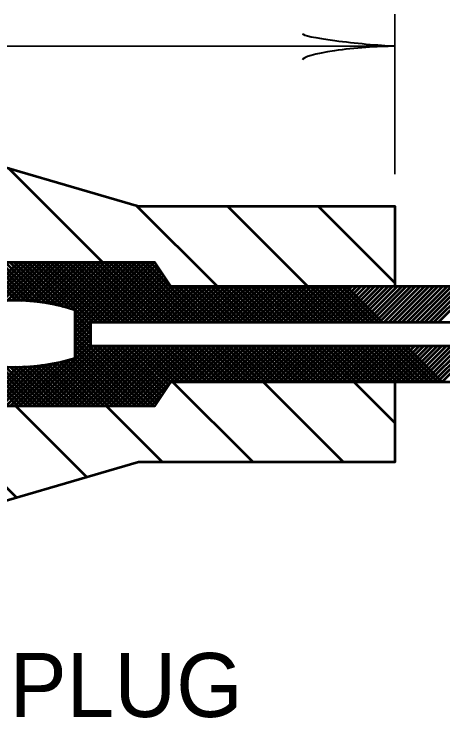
# Model space of a CAD drawing. Extents: x -1 to 679, y 0 to 440.
# Drawn here: x 534.27 to 547.66, y 229.08 to 251.07 of the extents above; entities that cross this region are included whole.
import ezdxf

# ---------------------------------------------------------------- set-up
doc = ezdxf.new("R2010")
doc.units = 0
doc.header["$LTSCALE"] = 0.8
doc.layers.add('1', color=7, linetype='Continuous', lineweight=53)

msp = doc.modelspace()

# ---------------------------------------------------------------- linework, layer by layer
at = {"layer": '1', "lineweight": 35}
for p, q in [((546.1543, 246.0712), (546.1543, 251.0712)), ((484.1543, 250.0712), (546.1543, 250.0712))]:
    msp.add_line(p, q, dxfattribs=at)
at = {"layer": '1'}
for p, q in [((537.0252, 243.3212), (534.0897, 246.2567)), ((540.6036, 242.5712), (538.0828, 245.0922)), ((543.4321, 242.5712), (540.9321, 245.0712)), ((546.1543, 242.6774), (543.7605, 245.0712)), ((533.0808, 241.9989), (534.4032, 243.3212)), ((534.3386, 242.1226), (533.14, 243.3212)), ((533.2508, 242.0275), (534.5447, 243.3212)), ((534.4863, 242.1162), (533.2814, 243.3212)), ((533.4209, 242.0561), (534.6861, 243.3212)), ((534.6341, 242.1099), (533.4228, 243.3212)), ((534.7818, 242.1037), (533.5643, 243.3212)), ((533.5909, 242.0847), (534.8275, 243.3212)), ((534.9397, 242.0872), (533.7057, 243.3212)), ((533.7446, 242.0969), (534.9689, 243.3212)), ((535.1057, 242.0626), (533.8471, 243.3212)), ((533.8953, 242.1062), (535.1103, 243.3212)), ((535.2718, 242.0379), (533.9885, 243.3212)), ((534.0461, 242.1156), (535.2518, 243.3212)), ((535.438, 242.0132), (534.1299, 243.3212)), ((534.1969, 242.125), (535.3932, 243.3212)), ((535.6254, 241.9672), (534.2713, 243.3212)), ((534.3361, 242.1227), (535.5346, 243.3212)), ((535.8159, 241.9181), (534.4127, 243.3212)), ((534.4717, 242.1169), (535.676, 243.3212)), ((536.0065, 241.869), (534.5542, 243.3212)), ((534.6073, 242.1111), (535.8174, 243.3212)), ((536.6637, 241.3532), (534.6956, 243.3212)), ((534.7429, 242.1053), (535.9588, 243.3212)), ((536.712, 241.4462), (534.837, 243.3212)), ((534.8757, 242.0967), (536.1002, 243.3212)), ((536.8534, 241.4462), (534.9784, 243.3212)), ((534.9989, 242.0784), (536.2417, 243.3212)), ((536.9949, 241.4462), (535.1199, 243.3212)), ((535.122, 242.0602), (536.3831, 243.3212)), ((535.2452, 242.0418), (536.5245, 243.3212)), ((537.1363, 241.4462), (535.2613, 243.3212)), ((535.3682, 242.0236), (536.6659, 243.3212)), ((537.2777, 241.4462), (535.4027, 243.3212)), ((535.4886, 242.0024), (536.8074, 243.3212)), ((537.4192, 241.4462), (535.5442, 243.3212)), ((535.601, 241.9735), (536.9488, 243.3212)), ((537.5606, 241.4462), (535.6856, 243.3212)), ((535.7135, 241.9445), (537.0902, 243.3212)), ((535.8259, 241.9155), (537.2317, 243.3212)), ((537.702, 241.4462), (535.827, 243.3212)), ((535.9383, 241.8865), (537.3731, 243.3212)), ((537.8434, 241.4462), (535.9684, 243.3212)), ((536.0507, 241.8576), (537.5145, 243.3212)), ((537.9848, 241.4462), (536.1098, 243.3212)), ((536.1578, 241.8232), (537.6559, 243.3212)), ((536.1637, 241.6876), (537.7973, 243.3212)), ((536.1637, 241.5462), (537.9388, 243.3212)), ((536.1637, 241.4047), (538.0802, 243.3212)), ((536.1637, 241.2633), (538.2216, 243.3212)), ((536.1637, 241.1219), (538.363, 243.3212)), ((536.1637, 240.9805), (538.5044, 243.3212)), ((538.1263, 241.4462), (536.2513, 243.3212)), ((538.2677, 241.4462), (536.3927, 243.3212)), ((538.4091, 241.4462), (536.5341, 243.3212)), ((538.5505, 241.4462), (536.6755, 243.3212)), ((536.7708, 241.4462), (538.6458, 243.3212)), ((538.6919, 241.4462), (536.8169, 243.3212)), ((536.9122, 241.4462), (538.7075, 243.2415)), ((538.8333, 241.4462), (536.9583, 243.3212)), ((538.9747, 241.4462), (537.0997, 243.3212)), ((539.1162, 241.4462), (537.2412, 243.3212)), ((539.2576, 241.4462), (537.3826, 243.3212)), ((539.399, 241.4462), (537.524, 243.3212)), ((539.5405, 241.4462), (537.6655, 243.3212)), ((539.6819, 241.4462), (537.8069, 243.3212)), ((539.8233, 241.4462), (537.9483, 243.3212)), ((539.9647, 241.4462), (538.0897, 243.3212)), ((540.1062, 241.4462), (538.2312, 243.3212)), ((540.2476, 241.4462), (538.3726, 243.3212)), ((538.935, 242.9002), (538.514, 243.3212)), ((537.0537, 241.4462), (538.7641, 243.1567)), ((537.1951, 241.4462), (538.8207, 243.0717)), ((537.3365, 241.4462), (538.8773, 242.9869)), ((537.478, 241.4462), (538.9338, 242.9021)), ((537.6194, 241.4462), (538.9903, 242.8173)), ((537.7608, 241.4462), (539.0469, 242.7323)), ((537.9022, 241.4462), (539.1035, 242.6475)), ((538.0437, 241.4462), (539.1687, 242.5712)), ((538.1851, 241.4462), (539.3101, 242.5712)), ((538.3265, 241.4462), (539.4515, 242.5712)), ((538.4679, 241.4462), (539.5929, 242.5712)), ((538.6093, 241.4462), (539.7343, 242.5712)), ((538.7507, 241.4462), (539.8757, 242.5712)), ((538.8922, 241.4462), (540.0172, 242.5712)), ((539.0336, 241.4462), (540.1586, 242.5712)), ((539.175, 241.4462), (540.3, 242.5712)), ((540.389, 241.4462), (539.264, 242.5712)), ((539.3164, 241.4462), (540.4414, 242.5712)), ((540.5304, 241.4462), (539.4054, 242.5712)), ((539.4578, 241.4462), (540.5828, 242.5712)), ((540.6718, 241.4462), (539.5468, 242.5712)), ((539.5992, 241.4462), (540.7242, 242.5712)), ((540.8132, 241.4462), (539.6882, 242.5712)), ((539.7407, 241.4462), (540.8657, 242.5712)), ((540.9547, 241.4462), (539.8297, 242.5712)), ((539.8822, 241.4462), (541.0072, 242.5712)), ((541.0961, 241.4462), (539.9711, 242.5712)), ((540.0236, 241.4462), (541.1486, 242.5712)), ((541.2375, 241.4462), (540.1125, 242.5712)), ((540.165, 241.4462), (541.29, 242.5712)), ((541.3789, 241.4462), (540.2539, 242.5712)), ((540.3064, 241.4462), (541.4314, 242.5712)), ((541.5203, 241.4462), (540.3953, 242.5712)), ((540.4478, 241.4462), (541.5728, 242.5712)), ((541.6617, 241.4462), (540.5367, 242.5712)), ((540.5892, 241.4462), (541.7142, 242.5712)), ((541.8032, 241.4462), (540.6782, 242.5712)), ((540.7307, 241.4462), (541.8557, 242.5712)), ((541.9446, 241.4462), (540.8196, 242.5712)), ((540.8721, 241.4462), (541.9971, 242.5712)), ((542.0861, 241.4462), (540.9611, 242.5712)), ((541.0135, 241.4462), (542.1385, 242.5712)), ((542.2275, 241.4462), (541.1025, 242.5712)), ((541.1549, 241.4462), (542.2799, 242.5712)), ((542.3689, 241.4462), (541.2439, 242.5712)), ((541.2963, 241.4462), (542.4213, 242.5712)), ((542.5103, 241.4462), (541.3853, 242.5712)), ((541.4377, 241.4462), (542.5627, 242.5712)), ((542.6517, 241.4462), (541.5267, 242.5712)), ((541.5792, 241.4462), (542.7042, 242.5712)), ((542.7932, 241.4462), (541.6682, 242.5712)), ((541.7206, 241.4462), (542.8456, 242.5712)), ((542.9346, 241.4462), (541.8096, 242.5712)), ((541.862, 241.4462), (542.987, 242.5712)), ((543.076, 241.4462), (541.951, 242.5712)), ((542.0034, 241.4462), (543.1284, 242.5712)), ((543.2174, 241.4462), (542.0924, 242.5712)), ((542.1448, 241.4462), (543.2698, 242.5712)), ((543.3588, 241.4462), (542.2338, 242.5712)), ((542.2862, 241.4462), (543.4112, 242.5712)), ((543.5002, 241.4462), (542.3752, 242.5712)), ((542.4277, 241.4462), (543.5527, 242.5712)), ((543.6417, 241.4462), (542.5167, 242.5712)), ((542.5692, 241.4462), (543.6942, 242.5712)), ((543.7831, 241.4462), (542.6581, 242.5712)), ((542.7106, 241.4462), (543.8356, 242.5712)), ((543.9245, 241.4462), (542.7995, 242.5712)), ((542.852, 241.4462), (543.977, 242.5712)), ((544.0659, 241.4462), (542.9409, 242.5712)), ((542.9934, 241.4462), (544.1184, 242.5712)), ((544.2073, 241.4462), (543.0823, 242.5712)), ((543.1348, 241.4462), (544.2598, 242.5712)), ((544.3487, 241.4462), (543.2237, 242.5712)), ((543.2763, 241.4462), (544.4013, 242.5712)), ((544.4902, 241.4462), (543.3652, 242.5712)), ((543.4177, 241.4462), (544.5427, 242.5712)), ((544.6317, 241.4462), (543.5067, 242.5712)), ((543.5591, 241.4462), (544.6841, 242.5712)), ((544.7731, 241.4462), (543.6481, 242.5712)), ((543.7005, 241.4462), (544.8255, 242.5712)), ((544.9145, 241.4462), (543.7895, 242.5712)), ((543.8419, 241.4462), (544.9669, 242.5712)), ((545.0559, 241.4462), (543.9309, 242.5712)), ((543.9833, 241.4462), (545.1083, 242.5712)), ((545.1973, 241.4462), (544.0723, 242.5712)), ((544.1247, 241.4462), (545.2497, 242.5712)), ((545.3388, 241.4462), (544.2138, 242.5712)), ((544.2662, 241.4462), (545.3912, 242.5712)), ((545.4802, 241.4462), (544.3552, 242.5712)), ((544.4076, 241.4462), (545.5326, 242.5712)), ((545.6216, 241.4462), (544.4966, 242.5712)), ((544.549, 241.4462), (545.674, 242.5712)), ((545.763, 241.4462), (544.638, 242.5712)), ((544.6904, 241.4462), (545.8154, 242.5712)), ((544.8318, 241.4462), (545.9568, 242.5712)), ((544.9733, 241.4462), (546.0983, 242.5712)), ((545.1147, 241.4462), (546.2397, 242.5712)), ((545.2562, 241.4462), (546.3812, 242.5712)), ((545.3976, 241.4462), (546.5226, 242.5712)), ((545.539, 241.4462), (546.664, 242.5712)), ((545.6804, 241.4462), (546.8054, 242.5712)), ((545.8218, 241.4462), (546.9468, 242.5712)), ((545.9633, 241.4462), (547.0883, 242.5712)), ((546.1047, 241.4462), (547.2297, 242.5712)), ((546.2461, 241.4462), (547.3711, 242.5712)), ((546.3875, 241.4462), (547.5125, 242.5712)), ((546.5289, 241.4462), (547.6539, 242.5712)), ((546.6703, 241.4462), (547.7953, 242.5712)), ((546.8117, 241.4462), (547.9367, 242.5712)), ((546.9532, 241.4462), (548.0782, 242.5712)), ((547.0946, 241.4462), (548.2196, 242.5712)), ((547.236, 241.4462), (548.361, 242.5712)), ((547.3774, 241.4462), (548.5024, 242.5712)), ((547.5189, 241.4462), (548.6439, 242.5712)), ((536.1637, 241.8212), (536.1637, 240.3212)), ((536.6637, 241.2117), (536.1637, 241.7117)), ((536.6637, 241.0703), (536.1637, 241.5703)), ((536.6637, 240.9289), (536.1637, 241.4289)), ((536.1637, 240.8391), (536.6637, 241.3391)), ((536.6637, 240.7875), (536.1637, 241.2875)), ((536.1637, 240.6977), (536.6637, 241.1977)), ((538.4885, 238.8212), (536.1637, 241.1461)), ((536.1637, 240.5563), (536.6637, 241.0563)), ((538.3471, 238.8212), (536.1637, 241.0047)), ((534.7115, 238.8212), (536.6637, 240.7734)), ((536.1637, 240.4148), (536.6637, 240.9148)), ((538.2057, 238.8212), (536.1637, 240.8632)), ((534.853, 238.8212), (536.728, 240.6962)), ((534.9944, 238.8212), (536.8694, 240.6962)), ((535.1358, 238.8212), (537.0108, 240.6962)), ((535.2772, 238.8212), (537.1522, 240.6962)), ((535.4187, 238.8212), (537.2937, 240.6962)), ((535.5601, 238.8212), (537.4351, 240.6962)), ((535.7015, 238.8212), (537.5765, 240.6962)), ((535.8429, 238.8212), (537.7179, 240.6962)), ((535.9843, 238.8212), (537.8593, 240.6962)), ((536.1257, 238.8212), (538.0007, 240.6962)), ((538.0643, 238.8212), (536.1637, 240.7218)), ((537.9228, 238.8212), (536.1637, 240.5804)), ((536.2672, 238.8212), (538.1422, 240.6962)), ((536.4086, 238.8212), (538.2836, 240.6962)), ((536.55, 238.8212), (538.425, 240.6962)), ((536.6914, 238.8212), (538.5664, 240.6962)), ((538.6299, 238.8212), (536.7549, 240.6962)), ((536.8328, 238.8212), (538.7078, 240.6962)), ((538.7012, 238.8915), (536.8963, 240.6962)), ((536.9742, 238.8212), (538.8492, 240.6962)), ((538.7577, 238.9763), (537.0377, 240.6962)), ((537.1157, 238.8212), (538.9907, 240.6962)), ((538.8143, 239.0612), (537.1792, 240.6962)), ((537.2572, 238.8212), (539.1322, 240.6962)), ((538.8708, 239.146), (537.3206, 240.6962)), ((537.3986, 238.8212), (539.2736, 240.6962)), ((538.9274, 239.2308), (537.462, 240.6962)), ((537.54, 238.8212), (539.415, 240.6962)), ((538.984, 239.3157), (537.6034, 240.6962)), ((537.6814, 238.8212), (539.5564, 240.6962)), ((539.0406, 239.4006), (537.7449, 240.6962)), ((537.8228, 238.8212), (539.6978, 240.6962)), ((539.0971, 239.4854), (537.8863, 240.6962)), ((537.9642, 238.8212), (539.8392, 240.6962)), ((539.1537, 239.5702), (538.0277, 240.6962)), ((538.1057, 238.8212), (539.9807, 240.6962)), ((539.2942, 239.5712), (538.1692, 240.6962)), ((538.2471, 238.8212), (540.1221, 240.6962)), ((539.4356, 239.5712), (538.3106, 240.6962)), ((538.3885, 238.8212), (540.2635, 240.6962)), ((539.577, 239.5712), (538.452, 240.6962)), ((539.7184, 239.5712), (538.5934, 240.6962)), ((539.8598, 239.5712), (538.7348, 240.6962)), ((540.0013, 239.5712), (538.8763, 240.6962)), ((540.1427, 239.5712), (539.0177, 240.6962)), ((540.2841, 239.5712), (539.1591, 240.6962)), ((539.2799, 239.5712), (540.4049, 240.6962)), ((540.4255, 239.5712), (539.3005, 240.6962)), ((539.4213, 239.5712), (540.5463, 240.6962)), ((540.5669, 239.5712), (539.4419, 240.6962)), ((539.5627, 239.5712), (540.6877, 240.6962)), ((540.7083, 239.5712), (539.5833, 240.6962)), ((539.7042, 239.5712), (540.8292, 240.6962)), ((540.8497, 239.5712), (539.7247, 240.6962)), ((539.8456, 239.5712), (540.9706, 240.6962)), ((540.9912, 239.5712), (539.8662, 240.6962)), ((539.987, 239.5712), (541.112, 240.6962)), ((541.1326, 239.5712), (540.0076, 240.6962)), ((540.1284, 239.5712), (541.2534, 240.6962)), ((541.274, 239.5712), (540.149, 240.6962)), ((540.2698, 239.5712), (541.3948, 240.6962)), ((541.4155, 239.5712), (540.2905, 240.6962)), ((540.4112, 239.5712), (541.5362, 240.6962)), ((541.5569, 239.5712), (540.4319, 240.6962)), ((540.5527, 239.5712), (541.6777, 240.6962)), ((541.6983, 239.5712), (540.5733, 240.6962)), ((540.6942, 239.5712), (541.8192, 240.6962)), ((541.8397, 239.5712), (540.7147, 240.6962)), ((540.8356, 239.5712), (541.9606, 240.6962)), ((541.9812, 239.5712), (540.8562, 240.6962)), ((540.977, 239.5712), (542.102, 240.6962)), ((542.1226, 239.5712), (540.9976, 240.6962)), ((541.1184, 239.5712), (542.2434, 240.6962)), ((542.264, 239.5712), (541.139, 240.6962)), ((541.2598, 239.5712), (542.3848, 240.6962)), ((542.4054, 239.5712), (541.2804, 240.6962)), ((541.4013, 239.5712), (542.5263, 240.6962)), ((542.5468, 239.5712), (541.4218, 240.6962)), ((541.5427, 239.5712), (542.6677, 240.6962)), ((542.6882, 239.5712), (541.5632, 240.6962)), ((541.6841, 239.5712), (542.8091, 240.6962)), ((542.8297, 239.5712), (541.7047, 240.6962)), ((541.8255, 239.5712), (542.9505, 240.6962)), ((542.9711, 239.5712), (541.8461, 240.6962)), ((541.9669, 239.5712), (543.0919, 240.6962)), ((543.1125, 239.5712), (541.9875, 240.6962)), ((542.1083, 239.5712), (543.2333, 240.6962)), ((543.2539, 239.5712), (542.1289, 240.6962)), ((542.2497, 239.5712), (543.3747, 240.6962)), ((543.3953, 239.5712), (542.2703, 240.6962)), ((542.3912, 239.5712), (543.5162, 240.6962)), ((543.5367, 239.5712), (542.4117, 240.6962)), ((542.5326, 239.5712), (543.6576, 240.6962)), ((543.6782, 239.5712), (542.5532, 240.6962)), ((542.674, 239.5712), (543.799, 240.6962)), ((543.8196, 239.5712), (542.6946, 240.6962)), ((542.8154, 239.5712), (543.9404, 240.6962)), ((543.9611, 239.5712), (542.8361, 240.6962)), ((542.9568, 239.5712), (544.0818, 240.6962)), ((544.1025, 239.5712), (542.9775, 240.6962)), ((543.0983, 239.5712), (544.2233, 240.6962)), ((544.2439, 239.5712), (543.1189, 240.6962)), ((543.2397, 239.5712), (544.3647, 240.6962)), ((544.3853, 239.5712), (543.2603, 240.6962)), ((543.3812, 239.5712), (544.5062, 240.6962)), ((544.5267, 239.5712), (543.4017, 240.6962)), ((543.5226, 239.5712), (544.6476, 240.6962)), ((544.6682, 239.5712), (543.5432, 240.6962)), ((543.664, 239.5712), (544.789, 240.6962)), ((544.8096, 239.5712), (543.6846, 240.6962)), ((543.8054, 239.5712), (544.9304, 240.6962)), ((544.951, 239.5712), (543.826, 240.6962)), ((543.9468, 239.5712), (545.0718, 240.6962)), ((545.0924, 239.5712), (543.9674, 240.6962)), ((544.0883, 239.5712), (545.2133, 240.6962)), ((545.2338, 239.5712), (544.1088, 240.6962)), ((544.2297, 239.5712), (545.3547, 240.6962)), ((545.3752, 239.5712), (544.2502, 240.6962)), ((544.3711, 239.5712), (545.4961, 240.6962)), ((545.5167, 239.5712), (544.3917, 240.6962)), ((544.5125, 239.5712), (545.6375, 240.6962)), ((545.6581, 239.5712), (544.5331, 240.6962)), ((544.6539, 239.5712), (545.7789, 240.6962)), ((545.7995, 239.5712), (544.6745, 240.6962)), ((544.7953, 239.5712), (545.9203, 240.6962)), ((545.9409, 239.5712), (544.8159, 240.6962)), ((544.9367, 239.5712), (546.0617, 240.6962)), ((546.0823, 239.5712), (544.9573, 240.6962)), ((545.0782, 239.5712), (546.2032, 240.6962)), ((546.2237, 239.5712), (545.0987, 240.6962)), ((545.2196, 239.5712), (546.3446, 240.6962)), ((546.3652, 239.5712), (545.2402, 240.6962)), ((545.361, 239.5712), (546.486, 240.6962)), ((546.5067, 239.5712), (545.3817, 240.6962)), ((545.5024, 239.5712), (546.6274, 240.6962)), ((546.6481, 239.5712), (545.5231, 240.6962)), ((545.6439, 239.5712), (546.7689, 240.6962)), ((546.7895, 239.5712), (545.6645, 240.6962)), ((545.7853, 239.5712), (546.9103, 240.6962)), ((546.9309, 239.5712), (545.8059, 240.6962)), ((545.9267, 239.5712), (547.0517, 240.6962)), ((547.0723, 239.5712), (545.9473, 240.6962)), ((546.0682, 239.5712), (547.1932, 240.6962)), ((547.2138, 239.5712), (546.0888, 240.6962)), ((546.2096, 239.5712), (547.3346, 240.6962)), ((547.3552, 239.5712), (546.2302, 240.6962)), ((546.351, 239.5712), (547.476, 240.6962)), ((547.4966, 239.5712), (546.3716, 240.6962)), ((546.4924, 239.5712), (547.6174, 240.6962)), ((547.638, 239.5712), (546.513, 240.6962)), ((546.6338, 239.5712), (547.7588, 240.6962)), ((546.7753, 239.5712), (547.9003, 240.6962)), ((546.9167, 239.5712), (548.0417, 240.6962)), ((547.0581, 239.5712), (548.1831, 240.6962)), ((547.1995, 239.5712), (548.3245, 240.6962)), ((547.3409, 239.5712), (548.4659, 240.6962)), ((547.4823, 239.5712), (548.6073, 240.6962)), ((547.6237, 239.5712), (548.7487, 240.6962)), ((537.64, 238.8212), (536.1447, 240.3166)), ((537.7814, 238.8212), (536.1637, 240.439)), ((534.3872, 238.8212), (533.0349, 240.1736)), ((534.5287, 238.8212), (533.207, 240.1429)), ((534.6702, 238.8212), (533.3792, 240.1122)), ((533.863, 238.8212), (535.1514, 240.1097)), ((534.0044, 238.8212), (535.3157, 240.1324)), ((534.1458, 238.8212), (535.4798, 240.1552)), ((534.2872, 238.8212), (535.6636, 240.1976)), ((534.4287, 238.8212), (535.8515, 240.2441)), ((534.5701, 238.8212), (536.0394, 240.2905)), ((536.3672, 238.8212), (535.0876, 240.1008)), ((536.5086, 238.8212), (535.2118, 240.1181)), ((536.65, 238.8212), (535.336, 240.1352)), ((536.7914, 238.8212), (535.4602, 240.1525)), ((536.9328, 238.8212), (535.5778, 240.1763)), ((537.0743, 238.8212), (535.6912, 240.2044)), ((537.2157, 238.8212), (535.8045, 240.2324)), ((537.3572, 238.8212), (535.9179, 240.2605)), ((537.4986, 238.8212), (536.0312, 240.2885)), ((533.1559, 238.8212), (534.3861, 240.0514)), ((533.2973, 238.8212), (534.5323, 240.0563)), ((533.4388, 238.8212), (534.6786, 240.0611)), ((534.8116, 238.8212), (533.5442, 240.0886)), ((533.5802, 238.8212), (534.8248, 240.0659)), ((534.953, 238.8212), (533.6966, 240.0777)), ((533.7216, 238.8212), (534.9873, 240.0869)), ((535.0944, 238.8212), (533.8489, 240.0667)), ((535.2358, 238.8212), (534.0013, 240.0557)), ((535.3773, 238.8212), (534.1537, 240.0448)), ((535.5187, 238.8212), (534.2916, 240.0483)), ((535.6601, 238.8212), (534.4285, 240.0528)), ((535.8015, 238.8212), (534.5654, 240.0573)), ((535.9429, 238.8212), (534.7023, 240.0618)), ((536.0843, 238.8212), (534.8392, 240.0664)), ((536.2257, 238.8212), (534.9634, 240.0837)), ((541.7283, 237.0712), (539.2283, 239.5712)), ((544.5567, 237.0712), (542.0567, 239.5712)), ((546.1543, 238.302), (544.8851, 239.5712)), ((538.5299, 238.8212), (538.9032, 239.1945)), ((534.352, 235.9622), (531.493, 238.8212)), ((536.5417, 236.6009), (534.3214, 238.8212)), ((538.8998, 237.0712), (537.1498, 238.8212))]:
    msp.add_line(p, q, dxfattribs=at)
for points in [[(511.1543, 244.2994), (511.1543, 245.9353), (518.1543, 245.9353), (518.1543, 247.5712), (532.1543, 247.5712), (532.1543, 246.8212), (538.1543, 245.0712), (546.1543, 245.0712), (546.1543, 242.5712)], [(546.1543, 239.5712), (546.1543, 237.0712), (538.1543, 237.0712), (532.1543, 235.3212), (532.1543, 234.5712), (518.1543, 234.5712), (518.1543, 236.2072), (511.1543, 236.2072)]]:
    msp.add_lwpolyline(points, dxfattribs=at)
for points in [[(525.9137, 243.0494), (525.9137, 244.2994), (528.6543, 243.3212), (538.6543, 243.3212), (539.1543, 242.5712), (546.1543, 242.5712), (556.1543, 242.5712), (556.1543, 239.5712), (546.1543, 239.5712), (539.1543, 239.5712), (538.6543, 238.8212), (528.6543, 238.8212), (525.9137, 237.8431), (525.9137, 239.0931)], [(536.6637, 240.6962), (536.6637, 241.4462), (555.6547, 241.4462), (555.6547, 240.6962)]]:
    msp.add_lwpolyline(points, close=True, dxfattribs=at)
for centre, radius, start, end in [((534.2887, 236.2333), 5.8942, 71.45124, 108.54876), ((534.2887, 246.4965), 6.4537, 253.11016, 286.88984)]:
    msp.add_arc(centre, radius, start, end, dxfattribs=at)
at = {"layer": '1', "lineweight": 40}
for centre, major_axis, ratio, start_param, end_param in [((545.0338, 250.2829), (1.7565, -0.1757), 0.07063, 3.1407148, 5.41811), ((545.0631, 249.795), (1.7857, 0.1562), 0.122415, 0.8963533, 3.1415927)]:
    msp.add_ellipse(centre, major_axis=major_axis, ratio=ratio, start_param=start_param, end_param=end_param, dxfattribs=at)

# ---------------------------------------------------------------- texts
at = {"layer": '1'}
msp.add_text('PLUG', height=2, dxfattribs=at).set_placement((534.1252, 229.1132))

doc.saveas('drawing.dxf')
